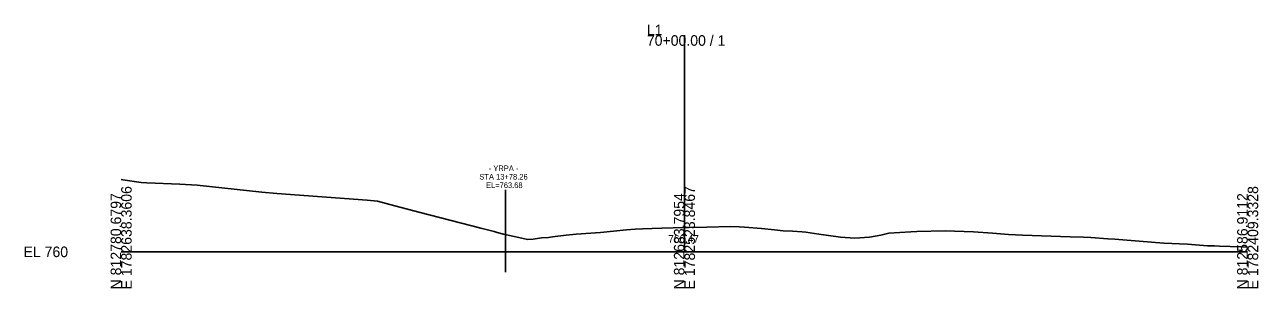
# Model space of a CAD drawing. Extents: x 5574 to 10203, y -10 to 9546.
# Drawn here: x 7574.3 to 7902.8, y 7490.3 to 7560.4 of the extents above; entities that cross this region are included whole.
import ezdxf

# ---------------------------------------------------------------- set-up
doc = ezdxf.new("R2010")
doc.units = 0
for name, color, linetype in [('Exist Cross Section Cell', 7, 'Continuous'), ('Exist XS Center Line Elevation Label', 7, 'Continuous'), ('Exist XS Ground Line', 7, 'Continuous'), ('Prop XS Vertical Lines Alignments', 7, 'Continuous')]:
    doc.layers.add(name, color=color, linetype=linetype)

msp = doc.modelspace()

# ---------------------------------------------------------------- linework, layer by layer
at = {"layer": 'Exist Cross Section Cell'}
for p, q in [((7750, 7500), (7750, 7557.61)), ((7600, 7500), (7750, 7500)), ((7750, 7500), (7900, 7500))]:
    msp.add_line(p, q, dxfattribs=at)
at = {"layer": 'Exist XS Ground Line'}
for p, q in [((7600, 7519.2), (7600.41, 7519.17)), ((7600.41, 7519.17), (7605.29, 7518.42)), ((7605.29, 7518.42), (7606.83, 7518.35)), ((7606.83, 7518.35), (7615.61, 7518.04)), ((7615.61, 7518.04), (7620.28, 7517.74)), ((7620.28, 7517.74), (7637.44, 7515.91)), ((7637.44, 7515.91), (7641.46, 7515.52)), ((7641.46, 7515.52), (7665.48, 7513.78)), ((7665.48, 7513.78), (7668.31, 7513.52)), ((7668.31, 7513.52), (7672.9, 7512.22)), ((7672.9, 7512.22), (7679.59, 7510.5)), ((7679.59, 7510.5), (7695.77, 7506.32)), ((7695.77, 7506.32), (7699.33, 7505.39)), ((7699.33, 7505.39), (7700.11, 7505.18)), ((7700.11, 7505.18), (7701.85, 7504.73)), ((7701.85, 7504.73), (7708.29, 7503.31)), ((7709.73, 7503.37), (7711.91, 7503.75)), ((7711.91, 7503.75), (7713.82, 7503.81)), ((7713.82, 7503.81), (7714.88, 7504.01)), ((7714.88, 7504.01), (7718.51, 7504.42)), ((7718.51, 7504.42), (7721.16, 7504.74)), ((7721.16, 7504.74), (7727.67, 7505.13)), ((7727.67, 7505.13), (7734.55, 7505.85)), ((7734.55, 7505.85), (7736.9, 7506.01)), ((7736.9, 7506.01), (7738.82, 7506.13)), ((7738.82, 7506.13), (7743.96, 7506.29)), ((7743.96, 7506.29), (7750, 7506.47)), ((7750, 7506.47), (7751.25, 7506.51)), ((7751.25, 7506.51), (7755.95, 7506.6)), ((7755.95, 7506.6), (7762.25, 7506.73)), ((7762.25, 7506.73), (7764.54, 7506.63)), ((7764.54, 7506.63), (7766.04, 7506.57)), ((7766.04, 7506.57), (7770.49, 7506.18)), ((7770.49, 7506.18), (7774.02, 7505.87)), ((7774.02, 7505.87), (7776.31, 7505.58)), ((7776.31, 7505.58), (7778.79, 7505.52)), ((7778.79, 7505.52), (7781.34, 7505.32)), ((7781.34, 7505.32), (7782.34, 7505.24)), ((7782.34, 7505.24), (7785.76, 7504.74)), ((7785.76, 7504.74), (7791.54, 7503.92)), ((7791.54, 7503.92), (7795.35, 7503.61)), ((7795.35, 7503.61), (7799.25, 7503.93)), ((7799.25, 7503.93), (7802.31, 7504.44)), ((7802.31, 7504.44), (7804.44, 7504.98)), ((7804.44, 7504.98), (7810.3, 7505.29)), ((7810.3, 7505.29), (7811.92, 7505.43)), ((7811.92, 7505.43), (7819.41, 7505.56)), ((7819.41, 7505.56), (7827, 7505.32)), ((7827, 7505.32), (7832.06, 7504.93)), ((7832.06, 7504.93), (7836.33, 7504.57)), ((7836.33, 7504.57), (7840.06, 7504.48)), ((7840.06, 7504.48), (7852.76, 7504.01)), ((7852.76, 7504.01), (7856.31, 7503.91)), ((7856.31, 7503.91), (7858.22, 7503.8)), ((7858.22, 7503.8), (7862.75, 7503.49)), ((7708.29, 7503.31), (7709.73, 7503.37)), ((7862.75, 7503.49), (7864.62, 7503.37)), ((7864.62, 7503.37), (7871.1, 7502.82)), ((7871.1, 7502.82), (7877.67, 7502.3)), ((7877.67, 7502.3), (7883.95, 7502)), ((7883.95, 7502), (7889.27, 7501.63)), ((7889.27, 7501.63), (7891.17, 7501.64)), ((7891.17, 7501.64), (7892.46, 7501.52)), ((7892.46, 7501.52), (7898.15, 7501.32)), ((7898.15, 7501.32), (7900, 7501.23))]:
    msp.add_line(p, q, dxfattribs=at)
at = {"layer": 'Prop XS Vertical Lines Alignments'}
msp.add_line((7702.32, 7516.47), (7702.32, 7494.62), dxfattribs=at)

# ---------------------------------------------------------------- texts
at = {"layer": 'Exist Cross Section Cell'}
for s, p in [('L1', (7740, 7557.61)), ('70+00.00 / 1', (7740, 7554.81)), ('EL 760', (7574, 7498.6))]:
    msp.add_text(s, height=2.8, dxfattribs=at).set_placement(p)
for s, p in [('E 1782638.3606', (7602.8, 7490)), ('E 1782523.8467', (7752.8, 7490)), ('E 1782409.3328', (7902.8, 7490)), ('N 812780.6797', (7600, 7490)), ('N 812683.7954', (7750, 7490)), ('N 812586.9112', (7900, 7490))]:
    msp.add_text(s, height=2.8, rotation=90, dxfattribs=at).set_placement(p)
at = {"layer": 'Exist XS Center Line Elevation Label'}
msp.add_text('766.47', height=2, dxfattribs=at).set_placement((7745.7, 7502.47))
at = {"layer": 'Prop XS Vertical Lines Alignments'}
for s, p in [('STA 13+78.26', (7695.38, 7519.22)), ('- YRPA -', (7697.89, 7521.47)), ('EL=763.68', (7697.15, 7516.97))]:
    msp.add_text(s, height=1.5, dxfattribs=at).set_placement(p)

doc.saveas('drawing.dxf')
